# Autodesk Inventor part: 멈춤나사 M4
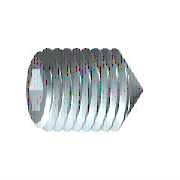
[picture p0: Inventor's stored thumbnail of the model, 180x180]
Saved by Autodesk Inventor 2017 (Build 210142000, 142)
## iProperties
Created: 2012-02
Part Number: 멈춤나사 M4
Material: 강철, 연강
Description: 6각 소켓 머리 없는 멈춤 나사
Document SubType Name: Modeling
Standard: KS B 1028
Designer: mduedu
Standards Organization: KS
Language: ko-KR
Size Designation: 원추점 M4x10
Categories: <MemberInstance><Categories><Category DisplayName="조임쇠" InternalName="e4da775c-781d-43d5-af7c-5136215cf5a6" Mnemonic="FSTN"><Category DisplayName="볼트" InternalN
Density: 7.86 g/cm^3
Mass: 0.792069 g
Surface Area: 1.48192 cm^2
Volume: 0.100772 cm^3
Appearance: 강철
Author: mduedu
IsCustomPart: 1
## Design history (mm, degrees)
sketch "스케치1"
  geometry: L1 (0, 0)-(6.833, 0); L2 (10, 1.155)-(10, 2); L3 (10, 2)-(0, 2); L4 (10, 1.155)-(7.5, 1.155); L5 (7.5, 1.155)-(6.833, 0); L6 (0, -0.4)-(0, 2.4) reference; L7 (0, 2)-(0, 0)
  constraints: 13 end point, 3 parallel, 1 collinear, 1 perpendicular, 1 point on line
  dimensions: "d0" = 2.5 distance of L2.start L4.end (= INTI); "d1" = 60 deg angle of L5 L1; "d2" = 4 diameter of L3 L1 (= NND); "d3" = 2.3094 diameter of L4 L1 (= 1.1547 x SW); "d5" = 10 distance from line of L2 L3.end (= NLG)
revolve "본체" sketch "스케치1" stored, may be unused: angle "d6" = 90 deg
sketch "스케치2"
  geometry: L1 (-0.577, 1)-(0.577, 1); L2 (0.577, 1)-(1.155, 0); L3 (1.155, 0)-(0.577, -1); L4 (0.577, -1)-(-0.577, -1); L5 (-0.577, -1)-(-1.155, 0); L6 (-1.155, 0)-(-0.577, 1); 3 further points
  constraints: 12 end point, 1 coincident, 1 horizontal, 13 other
extrude "슬롯" join sketch "스케치2" taper "d7" = 0 deg; stored distance "d21" = 10
workaxis "Work Axis1"
workplane "Work Plane1"
sketch "스케치4"
  geometry: L1 (-5, 0.2)-(-3.2, 2) reference; L2 (-5, -0.2)-(-3.2, -2) reference; L3 (-3.2, 2)-(-5.2, 0); L4 (-3.2, -2)-(-5.2, 0); 2 further points
  constraints: 4 end point, 2 collinear, 1 coincident
body "Solid1"
feature "스레드" dims "d12" = 10 (= NLG), "d13" = 0
chamfer "모따기1" distance "d8" = 1.8 (computed from NND, SPD, FAWI); stored, may be unused: angle "d9" = 45 deg (= FAWI), second distance "d34" = 1.8 (computed from NND, SPD, FAWI)
chamfer "모따기2" distance "d10" = 0.42941 (= -0.5 x GD1 + 0.5 x NND); stored, may be unused: angle "d11" = 45 deg (= FAWI), second distance "d35" = 0.42941 (= -0.5 x GD1 + 0.5 x NND)
other parameters: "NND" = 4 [user parameter; used in 5 equation terms], "NLG" = 10 [user parameter; used in 2 equation terms], "INTI" = 2.5 [user parameter; used in 1 equation term], "FAWI" = 45 deg [user parameter; used in 4 equation terms], "SW" = 2 [user parameter; used in 2 equation terms], "GD1" = 3.14117 (= THREADDIA - 1.2269 x PTC) [user parameter; used in 2 equation terms], "d4" = 0, "FAWI1" = 45 deg [user parameter], "SPD" = 0.4 [user parameter; used in 2 equation terms], "d36" = 0, "d37" = 0, "GUL" = 0.42941 (= 0.61345 x PTC) [user parameter], "TPU" = 14.28571 (computed from PTC) [user parameter], "TOA" = 30 deg [user parameter], "THREADDIA" = 4 [user parameter; used in 1 equation term], "PTC" = 0.7 [user parameter; used in 4 equation terms], "GAL" = 0.42941 (= 0.61345 x PTC) [user parameter], "E0" = 2.31 (= 1.155 x SW) [user parameter]
